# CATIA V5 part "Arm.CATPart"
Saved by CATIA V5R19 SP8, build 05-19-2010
Part number: Arm
Bounding box of the stored display mesh (mm): x -60 to 0, y -15 to 315, z -15 to 15
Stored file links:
  G:\EU_thinkMotion\CFAO_2010\MMS_groupe1\MMS_groupe1\OK\ptangsittisin\TANGSITTISIN\TANGSITTISIN\Arm.CATPart
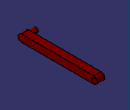
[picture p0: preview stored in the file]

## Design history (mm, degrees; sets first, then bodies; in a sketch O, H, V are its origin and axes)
Parameters
  `Arm Length` = 300 mm
Body1 (main body)
  Sketch1 on yz-plane, origin (0, 0, 0), H (0, 1, 0), V (0, 0, 1)
    point P1 (0, 15)
    line L1 (0, 15) -> (300, 15)
    construction line L2 (300, 15) -> (300, -15)
    line L3 (300, -15) -> (0, -15)
    construction line L4 (0, -15) -> (0, 15)
    point P2 (300, 15)
    point P3 (300, -15)
    point P4 (0, -15)
    arc A1 centre (300, 0) radius 15 from (300, -15) to (300, 15) ccw
    point P5 (300, 0)
    point P6 (300, -15)
    point P7 (300, 15)
    arc A2 centre (0, 0) radius 15 from (0, 15) to (0, -15) ccw
    point P8 (0, 15)
    point P9 (0, -15)
    length L1 = 300 {= `Arm Length`}
    distance L1 L3 = 30 {= `Arm Length` /10}
    distance O P5 = 300 {= `Arm Length`}
    distance P5 L3 = 15 {= `Arm Length` /20}
    distance O L3 = 15 {= `Arm Length` /20}
    radius A1 = 15 {= `Arm Length` /20}
    radius A2 = 15 {= `Arm Length` /20}
    length L3 = 300 {= `Arm Length`}
    coincidence: P1 P8, P2 P7, P3 P6, P4 P9
  Pad1: profile Sketch1, direction (-1, 0, 0), length 30
  Sketch2 on end face of Pad1, origin (-30, 0, 0), H (0, -1, 0), V (0, 0, 1)
    circle A1 centre (0, 0) radius 10
    radius A1 = 10
  Pad2: profile Sketch2, direction (-1, 0, 0), length 30
  Sketch3 on end face of Pad1, origin (-30, 0, 0), H (0, -1, 0), V (0, 0, 1)
    circle A1 centre (-300, 0) radius 10
    radius A1 = 10
  Pocket1: profile Sketch3, direction (1, 0, 0), through (limit type 6)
